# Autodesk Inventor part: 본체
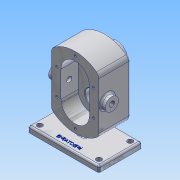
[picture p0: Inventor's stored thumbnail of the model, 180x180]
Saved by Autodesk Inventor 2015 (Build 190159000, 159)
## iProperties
Created: 2019-03
Part Number: 본체
Material: 알루미늄 6061
Document SubType Name: Modeling
Designer: user
Density: 2.7 g/cm^3
Appearance: 알루미늄 - 평지
Author: user
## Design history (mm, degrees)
sketch "스케치2"
  geometry: L1 (-60, -36.5)-(60, -36.5); L2 (60, -36.5)-(60, 36.5); L3 (60, 36.5)-(-60, 36.5); L4 (-60, 36.5)-(-60, -36.5); L5 (-60, -36.5)-(60, 36.5); L6 (60, -36.5)-(-60, 36.5); 1 further point
  constraints: 12 end point, 2 midpoint, 2 parallel, 1 horizontal, 1 perpendicular
  dimensions: "d2" = 120 distance of L2.end L3.end; "d3" = 73 distance of L1.end L2.end
extrude "돌출1" new body sketch "스케치2" distance "d4" = 10; taper "d5" = 0 deg
sketch "스케치3"
  geometry: L1 (120, 0)-(0, 0) reference; C1 r 60 at (60, -78); 2 further points
  constraints: 1 centre point, 1 midpoint, 1 vertical alignment
  dimensions: "d6" = 120 diameter of C1; "d7" = 78 distance from line of L1 C1.centre
extrude "돌출2" join sketch "스케치3" distance "d8" = 53; taper "d9" = 0 deg
sketch "스케치4"
  geometry: L1 (77.09, -63.961)-(40, -63.961); L2 (40, -63.961)-(40, 55.483); L3 (40, 55.483)-(77.09, 55.483); L4 (77.09, 55.483)-(77.09, -63.961); L5 (-40, -63.961)-(-71.773, -63.961); L6 (-71.773, -63.961)-(-71.773, 55.483); L7 (-71.773, 55.483)-(-40, 55.483); L8 (-40, 55.483)-(-40, -63.961); C1 r 60 at (0, 0) reference; 1 further point
  constraints: 16 end point, 4 parallel, 2 horizontal, 2 perpendicular, 2 point on line
  dimensions: "d11" = 40 distance from line of C1.centre L2; "d12" = 40 distance from line of L8 C1.centre
extrude "돌출3" cut sketch "스케치4" stored distance "d13" = 53; taper "d14" = 0 deg
sketch "스케치5"
  geometry: C1 r 19 at (60, -100); A1 r 60 centre (60, -78) between (100, -33.279) and (20, -33.279) reference; 1 further point
  constraints: 1 centre point, 1 vertical alignment
  dimensions: "d15" = 38 diameter of C1; "d16" = 22 distance of A1.centre C1.centre
extrude "돌출4" join sketch "스케치5" distance "d17" = 17; taper "d18" = 0 deg
sketch "스케치6"
  geometry: L1 (-36.5, 0)-(-36.5, 10) reference; L2 (-36.5, 10)-(36.5, 10) reference; L3 (36.5, 10)-(36.5, 0) reference; L4 (36.5, 0)-(-36.5, 0) reference; L5 (-16.5, 18)-(-16.5, 138) reference; L6 (-16.5, 138)-(36.5, 138) reference; L7 (36.5, 138)-(36.5, 119) reference; L8 (36.5, 119)-(53.5, 119) reference; L9 (53.5, 119)-(53.5, 81) reference; L10 (53.5, 81)-(36.5, 81) reference; L11 (36.5, 81)-(36.5, 18) reference; L12 (36.5, 18)-(-16.5, 18) reference; L13 (-6.5, 21.408)-(36.5, 21.408); L14 (36.5, 21.408)-(36.5, 7.41); L15 (36.5, 7.41)-(-6.5, 7.41); L16 (-6.5, 7.41)-(-6.5, 21.408); 1 further point
  constraints: 8 end point, 2 parallel, 1 horizontal, 1 perpendicular, 1 point on line
  dimensions: "d19" = 43 distance between parallel lines of L16 L14
extrude "돌출5" join sketch "스케치6" stored distance "d20" = 12; taper "d21" = 0 deg
sketch "스케치7"
  geometry: L1 (36, 100)-(36, 56); L2 (84, 100)-(84, 56); A1 r 60 centre (60, 78) between (100, 122.721) and (20, 122.721) reference; A2 r 24 centre (60, 100) between (84, 100) and (36, 100); A3 r 24 centre (60, 56) between (36, 56) and (84, 56); 1 further point
  constraints: 4 end point, 4 point on circle, 2 centre point, 2 horizontal alignment, 2 tangent, 2 vertical alignment
  dimensions: "d22" = 48 diameter of A2; "d23" = 22 distance of A1.centre A2.centre; "d24" = 48 diameter of A3; "d25" = 22 distance of A3.centre A1.centre
extrude "돌출6" cut sketch "스케치7" distance "d26" = 29; taper "d27" = 0 deg
sketch "스케치8"
  geometry: L1 (53.5, 81)-(36.5, 81) reference; L2 (36.5, 81)-(36.5, 0) reference; L3 (36.5, 0)-(-36.5, 0) reference; L4 (-36.5, 0)-(-36.5, 10) reference; L5 (-36.5, 10)-(-6.5, 10) reference; L6 (-6.5, 10)-(-6.5, 18) reference; L7 (-6.5, 18)-(-16.5, 18) reference; L8 (-16.5, 18)-(-16.5, 32) reference; L9 (-16.5, 32)-(12.5, 32) reference; L10 (12.5, 32)-(12.5, 124) reference; L11 (12.5, 124)-(-16.5, 124) reference; L12 (-16.5, 124)-(-16.5, 138) reference; L13 (-16.5, 138)-(36.5, 138) reference; L14 (36.5, 138)-(36.5, 119) reference; L15 (36.5, 119)-(53.5, 119) reference; L16 (53.5, 119)-(53.5, 81) reference; L17 (53.5, 100)-(12.5, 100); L18 (12.5, 112.5)-(27.5, 112.5); L19 (27.5, 112.5)-(27.5, 108.5); L20 (27.5, 108.5)-(46.2, 108.5); L21 (46.2, 108.5)-(46.2, 113.5); L22 (46.7, 114)-(52.8, 114); L23 (12.5, 100)-(12.5, 112.5); L24 (52.8, 114)-(53.5, 114.404); L25 (53.5, 114.404)-(53.5, 100); A1 r 0.5 centre (46.7, 113.5) between (46.7, 114) and (46.2, 113.5); 3 further points; 1 other entity
  constraints: 18 end point, 5 perpendicular, 5 point on line, 2 point on circle, 2 tangent, 1 centre point, 1 collinear, 1 horizontal, 1 horizontal alignment, 1 midpoint, 1 vertical, 2 other
  dimensions: "d28" = 15 distance between parallel lines of L10 L19; "d29" = 7.3 distance between parallel lines of L16 L21; "d30" = 30 deg angle of L22 L24; "d31" = 0.7 distance from line of L16 L22.end; "d32" = 0.5 radius of A1; "d33" = 28 diameter of L22 L17; "d34" = 17 diameter of L20 L17; "d35" = 25 diameter of L18 L17
revolve "회전1" sketch "스케치8" stored, may be unused: angle "d36" = 90 deg
sketch "스케치9"
  geometry: L1 (36.5, 119)-(53.5, 119) reference; L2 (53.5, 119)-(53.5, 114.404) reference; L3 (53.5, 114.404)-(52.8, 114) reference; L4 (52.8, 114)-(46.7, 114) reference; L5 (46.2, 113.5)-(46.2, 108.5) reference; L6 (46.2, 108.5)-(27.5, 108.5) reference; L7 (27.5, 108.5)-(27.5, 112.5) reference; L8 (27.5, 112.5)-(12.5, 112.5) reference; L9 (12.5, 112.5)-(12.5, 124) reference; L10 (12.5, 124)-(-16.5, 124) reference; L11 (-16.5, 124)-(-16.5, 138) reference; L12 (-16.5, 138)-(36.5, 138) reference; L13 (36.5, 138)-(36.5, 119) reference; L14 (53.5, 81)-(36.5, 81) reference; L15 (36.5, 81)-(36.5, 0) reference; L16 (36.5, 0)-(-36.5, 0) reference; L17 (-36.5, 0)-(-36.5, 10) reference; L18 (-36.5, 10)-(-6.5, 10) reference; L19 (-6.5, 10)-(-6.5, 18) reference; L20 (-6.5, 18)-(-16.5, 18) reference; L21 (-16.5, 18)-(-16.5, 32) reference; L22 (-16.5, 32)-(12.5, 32) reference; L23 (12.5, 32)-(12.5, 87.5) reference; L24 (12.5, 87.5)-(27.5, 87.5) reference; L25 (27.5, 87.5)-(27.5, 91.5) reference; L26 (27.5, 91.5)-(46.2, 91.5) reference; L27 (46.2, 91.5)-(46.2, 86.5) reference; L28 (46.7, 86)-(52.8, 86) reference; L29 (52.8, 86)-(53.5, 85.596) reference; L30 (53.5, 85.596)-(53.5, 81) reference; L31 (12.5, 68.5)-(27.5, 68.5); L32 (27.5, 68.5)-(27.5, 56); L33 (27.5, 56)-(12.5, 56); L34 (12.5, 56)-(12.5, 68.5); L35 (68.088, 100)-(-35.871, 100); A1 r 0.5 centre (46.7, 113.5) between (46.7, 114) and (46.2, 113.5) reference; A2 r 0.5 centre (46.7, 86.5) between (46.2, 86.5) and (46.7, 86) reference; 1 further point
  constraints: 10 end point, 2 horizontal, 2 parallel, 1 perpendicular, 1 point on line
  dimensions: "d37" = 8.5 distance between parallel lines of L35 L6; "d38" = 44 distance between parallel lines of L33 L35; "d39" = 25 diameter of L31 L33; "d40" = 15 distance between parallel lines of L34 L32
revolve "회전2" sketch "스케치9" stored, may be unused: angle "d41" = 90 deg
node "작업 평면1"
sketch "스케치10"
  geometry: L1 (-16.5, 33.279)-(-16.5, 122.721) reference; L2 (-36.5, 10)-(36.5, 10) reference; L3 (36.5, 10)-(36.5, 0) reference; L4 (36.5, 0)-(-36.5, 0) reference; L5 (-36.5, 0)-(-36.5, 10) reference; L6 (36.5, 138)-(-16.5, 138) reference; L7 (-6.5, 18)-(-16.5, 18) reference; L8 (67.752, 100)-(-71.921, 100); L9 (36.5, 119)-(53.5, 119) reference; L10 (53.5, 81)-(53.5, 119) reference; L11 (36.5, 119)-(36.5, 81) reference; L12 (36.5, 81)-(53.5, 81) reference; C1 r 11 at (-2.5, 78); 1 further point
  constraints: 2 end point, 1 centre point, 1 horizontal
  dimensions: "d43" = 22 diameter of C1; "d44" = 14 distance from line of L1 C1.centre; "d45" = 19 distance between parallel lines of L8 L9; "d46" = 22 distance from line of C1.centre L8
extrude "돌출7" join sketch "스케치10" stored distance "d47" = 29; taper "d48" = 0 deg
hole "구멍1" diameter "d51" = 8.917; stored, may be unused: countersink angle "d55" = 90 deg, drill point angle "d57" = 118 deg; dims "d49" = 10, "d50" = 10, "d52" = 20, "d53" = 4, "d54" = 2, "d56" = 25.1
sketch "스케치11"
  geometry: A1 r 24 centre (60, 100) between (84, 100) and (36, 100) reference; 2 further points
  constraints: 1 vertical alignment
  dimensions: "d58" = 31 distance of A1.centre point (60, 131)
hole "구멍2" sketch "스케치11" at (60, 131) diameter "d59" = 4.134; stored, may be unused: countersink angle "d63" = 90 deg, drill point angle "d65" = 120 deg; dims "d60" = 10, "d61" = 4, "d62" = 2, "d64" = 12
node "작업 평면2"
sketch "스케치12"
  geometry: L1 (-6, 36.5)-(-60, 36.5) reference; L2 (-60, 36.5)-(-60, -36.5) reference; C1 r 4.5 at (-50, 26.5); 1 further point
  constraints: 1 centre point
  dimensions: "d70" = 9 diameter of C1; "d71" = 10 distance from line of L1 C1.centre; "d72" = 10 distance from line of L2 C1.centre
extrude "돌출8" cut sketch "스케치12" stored distance "d73" = 29; taper "d74" = 0 deg
chamfer "모따기1" distance "d81" = 1; stored, may be unused: second distance "d82" = 2, angle "d83" = 45 deg
fillet "모깎기1" dims "d84" = 10
fillet "모깎기2" dims "d85" = 3
fillet "모깎기3" dims "d86" = 3
fillet "모깎기4" dims "d87" = 3
fillet "모깎기5" dims "d88" = 3
fillet "모깎기6" dims "d89" = 3
sketch "스케치13"
  geometry: L1 (-57, -36.5)-(57, -36.5) reference; L2 (-60, 33.5)-(-60, -33.5) reference; 2 further points
  constraints: 1 other
  dimensions: "d90" = 10 distance from line of L1 point (0, -26.5); "d91" = 60 distance from line of L2 point (0, -26.5)
feature "엠보싱1" sketch "스케치13" dims "d2" = 120, "d3" = 73, "d11" = 40, "d12" = 40, "d92" = 0.5, "d93" = 0
node "솔리드1"
mirror "대칭1"
pattern_circular "원형 패턴1" dims angle "d67" = 360 deg
mirror "대칭2"
pattern_linear "직사각형 패턴1" dims "d77" = 100, "d80" = 53
node "투영된 루프1"
node "절단 모서리 투영1"
node "절단 모서리 투영2"
node "절단 모서리 투영3"
node "절단 모서리 투영4"
other parameters: "d42" = 48, "d69" = 78
